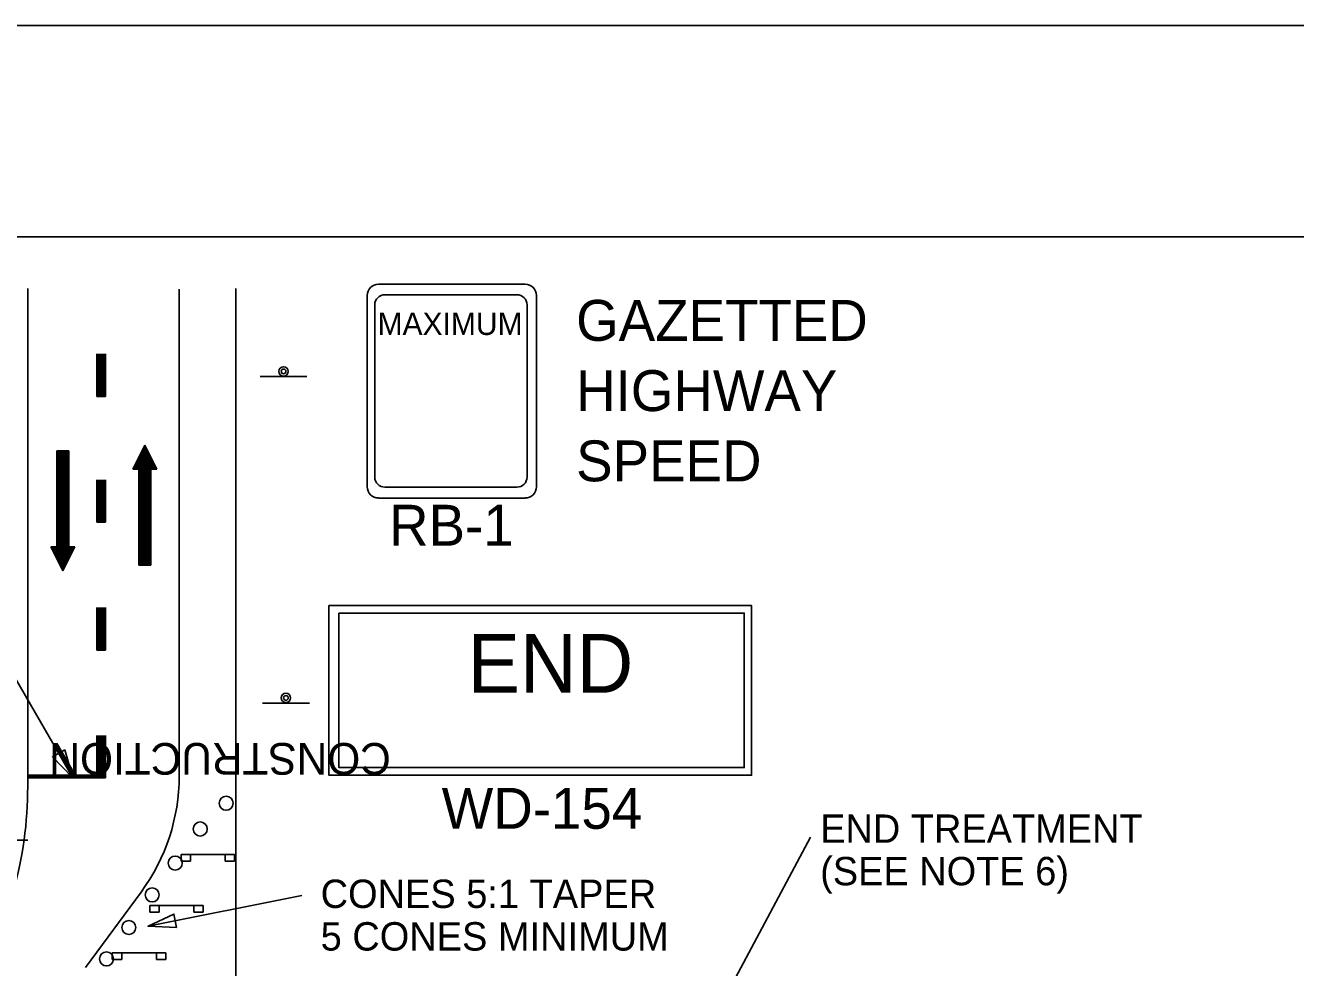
# Model space of a CAD drawing. Extents: x 2179 to 2395, y 134 to 413.
# Drawn here: x 2223.4 to 2288.3, y 364.6 to 412.8 of the extents above; entities that cross this region are included whole.
import ezdxf

# ---------------------------------------------------------------- set-up
doc = ezdxf.new("R2010")
doc.units = 0
for name, color, linetype in [('Level 10', 7, 'Continuous'), ('Level 2', 7, 'Continuous'), ('Level 44', 7, 'Continuous'), ('Level 5', 7, 'Continuous'), ('Level 60', 7, 'Continuous'), ('Level 7', 7, 'Continuous')]:
    doc.layers.add(name, color=color, linetype=linetype)

# ---------------------------------------------------------------- blocks, each defined once
blk = doc.blocks.new('END')
at = {"layer": 'Level 2'}
for points in [[(0, 8.676), (21.598, 8.676), (21.598, 0), (0, 0)], [(0.511, 8.287), (21.224, 8.287), (21.224, 0.397), (0.511, 0.397)]]:
    blk.add_lwpolyline(points, close=True, dxfattribs=at)
at = {"layer": 'Level 44'}
for s, height, rotation, p in [('END', 3, 359.99999, (7.085, 4.219)), ('CONSTRUCTION', 1.62, 179.99999, (3.164, 1.653))]:
    blk.add_text(s, height=height, rotation=rotation, dxfattribs=at).set_placement(p)

msp = doc.modelspace()

# ---------------------------------------------------------------- linework, layer by layer
at = {"layer": 'Level 10'}
for p, q in [((2223.547, 373.851), (2223.547, 399.312)), ((2231.288, 374.391), (2231.288, 399.282)), ((2234.191, 343.931), (2234.191, 399.312)), ((2225.039, 386.105), (2225.039, 391.013)), ((2225.652, 391.013), (2225.039, 391.013)), ((2225.039, 385.491), (2225.039, 391.013)), ((2225.115, 385.338), (2225.115, 391.013)), ((2225.192, 385.185), (2225.192, 391.013)), ((2225.269, 385.031), (2225.269, 391.013)), ((2225.345, 384.877), (2225.345, 391.013)), ((2225.421, 385.031), (2225.421, 391.013)), ((2225.5, 385.185), (2225.5, 391.013)), ((2225.575, 385.338), (2225.575, 391.013)), ((2225.652, 386.105), (2225.652, 391.013)), ((2225.652, 385.491), (2225.652, 391.013)), ((2229.537, 391.305), (2228.923, 390.078)), ((2229.307, 390.844), (2229.307, 385.17)), ((2229.382, 390.998), (2229.382, 385.17)), ((2229.461, 391.151), (2229.461, 385.17)), ((2229.537, 391.305), (2229.537, 385.17)), ((2229.537, 391.305), (2230.15, 390.078)), ((2229.613, 391.151), (2229.613, 385.17)), ((2229.69, 390.998), (2229.69, 385.17)), ((2229.767, 390.844), (2229.767, 385.17)), ((2229, 390.231), (2229, 390.078)), ((2229.076, 390.385), (2229.076, 390.078)), ((2229.153, 390.538), (2229.153, 390.078)), ((2229.23, 390.692), (2229.23, 385.17)), ((2229.843, 390.692), (2229.843, 385.17)), ((2229.92, 390.538), (2229.92, 390.078)), ((2229.997, 390.385), (2229.997, 390.078)), ((2230.074, 390.231), (2230.074, 390.078)), ((2228.923, 390.078), (2229.23, 390.078)), ((2229.23, 390.078), (2229.23, 385.17)), ((2229.843, 390.078), (2229.843, 385.17)), ((2229.843, 390.078), (2230.15, 390.078)), ((2225.345, 384.877), (2224.732, 386.105)), ((2225.039, 386.105), (2224.732, 386.105)), ((2224.808, 385.951), (2224.808, 386.105)), ((2224.885, 385.798), (2224.885, 386.105)), ((2224.962, 385.644), (2224.962, 386.105)), ((2225.345, 384.877), (2225.959, 386.105)), ((2225.959, 386.105), (2225.652, 386.105)), ((2225.729, 385.644), (2225.729, 386.105)), ((2225.806, 385.798), (2225.806, 386.105)), ((2225.882, 385.951), (2225.882, 386.105)), ((2219.405, 385.448), (2225.852, 374.301)), ((2229.23, 385.17), (2229.843, 385.17)), ((2227.087, 374.446), (2223.547, 374.446)), ((2227.087, 374.398), (2223.547, 374.398)), ((2227.087, 374.349), (2223.547, 374.349)), ((2227.087, 374.301), (2223.547, 374.301)), ((2223.547, 371.11), (2221.663, 371.11)), ((2231.387, 370.389), (2234.122, 370.389)), ((2231.387, 370.389), (2231.387, 370.05)), ((2231.387, 370.05), (2231.871, 370.05)), ((2231.871, 370.389), (2231.871, 370.05)), ((2233.639, 370.389), (2233.639, 370.05)), ((2233.639, 370.049), (2234.122, 370.049)), ((2234.122, 370.389), (2234.122, 370.049)), ((2226.503, 364.604), (2229.344, 368.467)), ((2229.787, 367.776), (2232.522, 367.776)), ((2229.787, 367.776), (2229.787, 367.437)), ((2230.271, 367.776), (2230.271, 367.437)), ((2232.039, 367.776), (2232.039, 367.437)), ((2232.522, 367.776), (2232.522, 367.436)), ((2229.787, 367.437), (2230.271, 367.437)), ((2232.039, 367.436), (2232.522, 367.436)), ((2227.871, 365.364), (2230.606, 365.364)), ((2227.871, 365.364), (2227.871, 365.025)), ((2227.871, 365.025), (2228.355, 365.025)), ((2228.355, 365.364), (2228.355, 365.025)), ((2230.123, 365.364), (2230.123, 365.025)), ((2230.123, 365.024), (2230.606, 365.024)), ((2230.606, 365.364), (2230.606, 365.024))]:
    msp.add_line(p, q, dxfattribs=at)
for centre in [(2233.689, 373.001), (2232.365, 371.686), (2231.086, 369.947), (2229.908, 368.319), (2228.716, 366.654), (2227.574, 365.045)]:
    msp.add_circle(centre, 0.359, dxfattribs=at)
msp.add_arc((2221.288, 374.391), 10, 323.66786, 0, dxfattribs=at)
at = {"layer": 'Level 2'}
msp.add_line((2227.161, 374.406), (2227.451, 374.406), dxfattribs=at)
for points in [[(2238.943, 383.108), (2260.541, 383.108), (2260.541, 374.432), (2238.943, 374.432)], [(2239.454, 382.719), (2260.167, 382.719), (2260.167, 374.829), (2239.454, 374.829)]]:
    msp.add_lwpolyline(points, close=True, dxfattribs=at)
at = {"layer": 'Level 44'}
for p, q in [((2241.477, 399.534), (2248.973, 399.534)), ((2240.899, 389.185), (2240.899, 398.955)), ((2241.805, 398.994), (2248.551, 398.994)), ((2249.553, 398.955), (2249.553, 389.185)), ((2241.286, 389.679), (2241.286, 398.474)), ((2249.073, 398.474), (2249.073, 389.679)), ((2235.421, 394.806), (2237.818, 394.806)), ((2227.522, 393.791), (2227.087, 393.791)), ((2241.286, 389.677), (2241.286, 389.679)), ((2240.899, 389.181), (2240.899, 389.185)), ((2248.551, 389.158), (2241.805, 389.158)), ((2248.973, 388.603), (2241.477, 388.603)), ((2227.522, 387.362), (2227.087, 387.362)), ((2227.522, 380.829), (2227.087, 380.829)), ((2237.948, 378.118), (2235.551, 378.118)), ((2227.522, 374.296), (2227.087, 374.296))]:
    msp.add_line(p, q, dxfattribs=at)
for points in [[(2227.087, 395.968), (2227.087, 393.791)], [(2227.16, 395.968), (2227.16, 393.791)], [(2227.232, 395.968), (2227.232, 393.791)], [(2227.305, 395.968), (2227.305, 393.791)], [(2227.377, 395.968), (2227.377, 393.791)], [(2227.45, 395.968), (2227.45, 393.791)], [(2227.522, 395.968), (2227.522, 393.791)], [(2227.087, 389.54), (2227.087, 387.362)], [(2227.16, 389.54), (2227.16, 387.362)], [(2227.232, 389.54), (2227.232, 387.362)], [(2227.305, 389.54), (2227.305, 387.362)], [(2227.377, 389.54), (2227.377, 387.362)], [(2227.45, 389.54), (2227.45, 387.362)], [(2227.522, 389.54), (2227.522, 387.362)], [(2227.087, 383.007), (2227.087, 380.829)], [(2227.16, 383.007), (2227.16, 380.829)], [(2227.232, 383.007), (2227.232, 380.829)], [(2227.305, 383.007), (2227.305, 380.829)], [(2227.377, 383.007), (2227.377, 380.829)], [(2227.45, 383.007), (2227.45, 380.829)], [(2227.522, 383.007), (2227.522, 380.829)], [(2227.087, 376.474), (2227.087, 374.296)], [(2227.16, 376.474), (2227.16, 374.296)], [(2227.232, 376.474), (2227.232, 374.296)], [(2227.305, 376.474), (2227.305, 374.296)], [(2227.377, 376.474), (2227.377, 374.296)], [(2227.45, 376.474), (2227.45, 374.296)], [(2227.522, 376.474), (2227.522, 374.296)]]:
    msp.add_lwpolyline(points, dxfattribs=at)
for centre, radius in [((2236.625, 395.075), 0.24), ((2236.625, 395.075), 0.12), ((2236.744, 378.387), 0.24), ((2236.744, 378.387), 0.12)]:
    msp.add_circle(centre, radius, dxfattribs=at)
for centre, radius, start, end in [((2241.478, 398.954), 0.578, 90, 179.99999), ((2248.973, 398.954), 0.578, 359.99999, 89.99999), ((2241.806, 398.472), 0.52, 90, 179.99999), ((2248.551, 398.472), 0.52, 359.99999, 89.99999), ((2241.806, 389.677), 0.52, 180, 269.99999), ((2248.551, 389.677), 0.52, 270, 359.99999), ((2241.478, 389.182), 0.578, 180, 269.99999), ((2248.973, 389.182), 0.578, 270, 359.99999)]:
    msp.add_arc(centre, radius, start, end, dxfattribs=at)
at = {"layer": 'Level 5'}
msp.add_line((2259.582, 363.833), (2263.56, 371.276), dxfattribs=at)
msp.add_lwpolyline([(2225.44, 375.739), (2225.852, 374.301), (2224.812, 375.375)], close=True, dxfattribs=at)
msp.add_arc((2203.547, 373.851), 20, 344.39375, 0, dxfattribs=at)
at = {"layer": 'Level 60'}
for points in [[(2394.748, 412.757), (2178.748, 412.757), (2178.748, 133.757), (2394.748, 133.757)], [(2375.622, 401.948), (2188.748, 401.948), (2188.748, 144.566), (2375.622, 144.566)]]:
    msp.add_lwpolyline(points, close=True, dxfattribs=at)
at = {"layer": 'Level 7'}
msp.add_line((2229.696, 366.714), (2237.551, 368.294), dxfattribs=at)
msp.add_lwpolyline([(2231.157, 366.646), (2229.696, 366.714), (2231.017, 367.342)], close=True, dxfattribs=at)

# ---------------------------------------------------------------- block references
at = {"layer": 'Level 2'}
msp.add_blockref('END', (2238.943, 374.432), dxfattribs=at)

# ---------------------------------------------------------------- texts
at = {"layer": 'Level 10'}
for s, height, p in [('GAZETTED ', 2.09, (2251.577, 396.636)), ('HIGHWAY', 2.09, (2251.577, 393.046)), ('SPEED', 2.09, (2251.577, 389.456)), ('RB-1', 2.09, (2242.017, 386.167)), ('WD-154', 2.09, (2244.704, 371.698)), ('END TREATMENT', 1.45, (2264.05, 370.98)), ('(SEE NOTE 6)', 1.45, (2264.05, 368.81)), ('CONES 5:1 TAPER', 1.4514, (2238.519, 367.65)), ('5 CONES MINIMUM', 1.4514, (2238.519, 365.474))]:
    msp.add_text(s, height=height, dxfattribs=at).set_placement(p)
at = {"layer": 'Level 44'}
for s, height, rotation, p in [('MAXIMUM', 1.1467, 360, (2241.427, 396.935)), ('CONSTRUCTION', 1.62023, 179.99999, (2242.106, 376.084))]:
    msp.add_text(s, height=height, rotation=rotation, dxfattribs=at).set_placement(p)

doc.saveas('drawing.dxf')
